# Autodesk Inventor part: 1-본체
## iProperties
Created: 2015-01
Part Number: 1-본체
Document SubType Name: Modeling
Designer: Administrator
Density: 2.71 g/cm^3
Material: 알루미늄-6061
Mass: 1021.34 g
Surface Area: 1059.8 cm^2
Volume: 376.879 cm^3
Author: Administrator
